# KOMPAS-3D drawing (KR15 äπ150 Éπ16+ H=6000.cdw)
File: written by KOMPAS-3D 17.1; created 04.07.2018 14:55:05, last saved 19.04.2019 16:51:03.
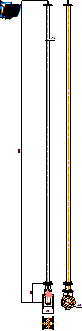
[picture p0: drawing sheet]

Sheet 1: A4, portrait

Title block, sheet 1: name: KR15 Ду150 Ру16+ / H=6000; material: Внимание! Данный продукт является объектом авторского права ООО «Торговый Дом АДЛ». / Запрещается изменение, копирование, распространение / (в том числе путем копирования на другие сайты и ресурсы в Интернете) / или любое иное использование информации и объектов без предварительного / согласия правообладателя (ООО «Торговый Дом АДЛ»).; mass: 36,7; sheets: 1; organisation: ООО "Торговый дом АДЛ"; sheet format: A4; stored path: \\adlc.lan\data\АДЛ_ПКД\3D-модели\ADL production\Клиновые задвижки серии KR ГРАНАР\Клиновые задвижки KR15 со стационарным удлинением\KOMPAS 2D\KR15 Ду150 Ру16+ H=6000.cdw

Views: Проекционный вид 6, Спереди 11, Проекционный вид 12
Referenced files in C:\Users\kka\KOMPAS_Work\!Trash\ГРАНАР KR Задвижки с приводами и удлинениями\С приводами\: KR15 Ду150 Ру16.m3d
Referenced files in C:\Users\kka\KOMPAS_Work\Удлинения БИВАЛ ф. ADL\!Задвижки\У_ду_125-400\: Ушду125-400.a3d
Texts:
  kka
  adl
  УШКЗ.100000.00.00
  Удлинение клиновой задвижки с редуктором
  Крепежное изделие ГОСТ
  Болт
  ГОСТ
  Гайка
  Лит-Масса-Масштаб
  Материал-Предприятие
  Title Specification
  Body Specification ( left align )
  Body Specificaton ( centered )
  Поз.
  Кол.
  Приме-
  чание
  Таблица спецификации
Dimensions and other numbers on the sheet: 6000; 76; 370; 210; 4; 1; 58; 40Х; 019; 1:1; 36,7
